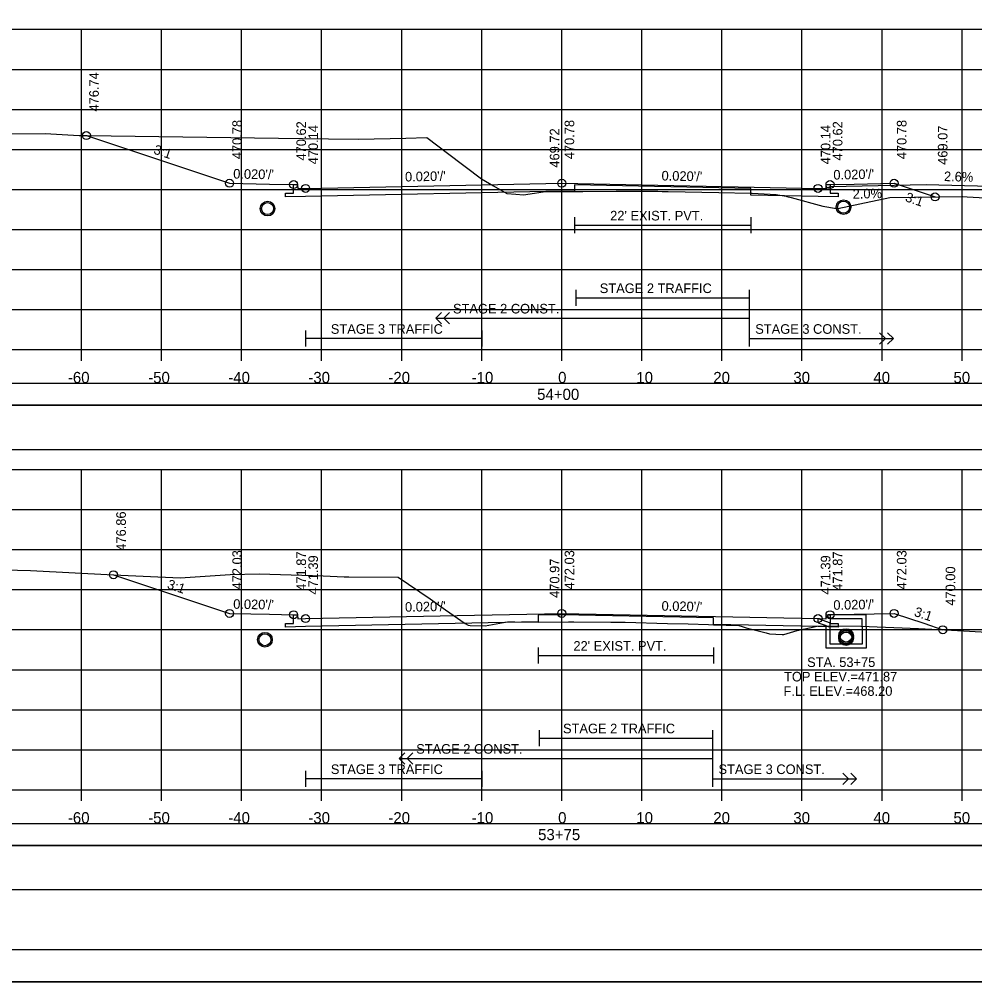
# Model space of a CAD drawing. Extents: x 1371057 to 1372761, y 380005 to 390517.
# Drawn here: x 1371826.4 to 1371945.8, y 383631.8 to 383752.1 of the extents above; entities that cross this region are included whole.
import ezdxf

# ---------------------------------------------------------------- set-up
doc = ezdxf.new("R2010")
doc.units = 0
for name, color, linetype in [('R_Alt Surface', 7, 'Continuous'), ('R_Axis', 7, 'Continuous'), ('R_Axis Annot', 7, 'Continuous'), ('R_Border', 7, 'Continuous'), ('R_Detour', 7, 'Continuous'), ('R_Dimension', 7, 'Continuous'), ('R_Drive', 7, 'Continuous'), ('R_Exist Surface', 7, 'Continuous'), ('R_Fin Surface', 7, 'Continuous'), ('R_Grid', 7, 'Continuous'), ('R_No Plot', 7, 'Continuous'), ('R_Striping', 7, 'Continuous'), ('R_Water', 7, 'Continuous'), ('R_Water Annot', 7, 'Continuous'), ('R_Xsect Elev', 7, 'Continuous'), ('R_Xsect Slope', 7, 'Continuous')]:
    doc.layers.add(name, color=color, linetype=linetype)

msp = doc.modelspace()

# ---------------------------------------------------------------- linework, layer by layer
at = {"layer": 'R_Alt Surface'}
for points in [[(1371927.71, 383731.42), (1371927.71, 383730.34), (1371928.71, 383730.32), (1371928.71, 383729.89), (1371926.21, 383729.94), (1371917.81, 383730.11), (1371917.81, 383730.94), (1371895.79, 383731.38), (1371895.79, 383730.55), (1371894.21, 383730.58), (1371862.21, 383729.94), (1371859.71, 383729.89), (1371859.71, 383730.32), (1371860.71, 383730.34), (1371860.71, 383731.42)], [(1371895.79, 383727.33), (1371895.79, 383725.33)], [(1371917.81, 383727.33), (1371917.81, 383725.33)], [(1371895.79, 383726.33), (1371917.81, 383726.33)], [(1371927.71, 383677.67), (1371927.71, 383676.59), (1371928.71, 383676.57), (1371928.71, 383676.14), (1371926.21, 383676.19), (1371913.17, 383676.45), (1371913.17, 383677.28), (1371894.21, 383677.66), (1371891.24, 383677.6), (1371891.24, 383676.77), (1371862.21, 383676.19), (1371859.71, 383676.14), (1371859.71, 383676.57), (1371860.71, 383676.59), (1371860.71, 383677.67)], [(1371891.24, 383673.58), (1371891.24, 383671.58)], [(1371913.17, 383673.58), (1371913.17, 383671.58)], [(1371891.24, 383672.58), (1371913.17, 383672.58)]]:
    msp.add_lwpolyline(points, dxfattribs=at)
at = {"layer": 'R_Axis'}
for p, q in [((1371744.21, 383710.81), (1372044.21, 383710.81)), ((1371834.21, 383709.41), (1371834.21, 383710.81)), ((1371844.21, 383709.41), (1371844.21, 383710.81)), ((1371854.21, 383709.41), (1371854.21, 383710.81)), ((1371864.21, 383709.41), (1371864.21, 383710.81)), ((1371874.21, 383709.41), (1371874.21, 383710.81)), ((1371884.21, 383709.41), (1371884.21, 383710.81)), ((1371894.21, 383709.41), (1371894.21, 383710.81)), ((1371904.21, 383709.41), (1371904.21, 383710.81)), ((1371914.21, 383709.41), (1371914.21, 383710.81)), ((1371924.21, 383709.41), (1371924.21, 383710.81)), ((1371934.21, 383709.41), (1371934.21, 383710.81)), ((1371944.21, 383709.41), (1371944.21, 383710.81)), ((1371744.21, 383655.81), (1372044.21, 383655.81)), ((1371834.21, 383654.41), (1371834.21, 383655.81)), ((1371844.21, 383654.41), (1371844.21, 383655.81)), ((1371854.21, 383654.41), (1371854.21, 383655.81)), ((1371864.21, 383654.41), (1371864.21, 383655.81)), ((1371874.21, 383654.41), (1371874.21, 383655.81)), ((1371884.21, 383654.41), (1371884.21, 383655.81)), ((1371894.21, 383654.41), (1371894.21, 383655.81)), ((1371904.21, 383654.41), (1371904.21, 383655.81)), ((1371914.21, 383654.41), (1371914.21, 383655.81)), ((1371924.21, 383654.41), (1371924.21, 383655.81)), ((1371934.21, 383654.41), (1371934.21, 383655.81)), ((1371944.21, 383654.41), (1371944.21, 383655.81))]:
    msp.add_line(p, q, dxfattribs=at)
at = {"layer": 'R_Border'}
msp.add_line((1372052.39, 383635.81), (1371736.21, 383635.81), dxfattribs=at)
at = {"layer": 'R_Detour'}
for points in [[(1371741.06, 383703.85), (1372047.37, 383703.85), (1372047.37, 383706.56), (1371741.06, 383706.56)], [(1371741.06, 383648.85), (1372047.37, 383648.85), (1372047.37, 383651.56), (1371741.06, 383651.56)]]:
    msp.add_lwpolyline(points, close=True, dxfattribs=at)
at = {"layer": 'R_Dimension'}
for points in [[(1371741.06, 383698.33), (1372047.37, 383698.33), (1372047.37, 383703.85), (1371741.06, 383703.85)], [(1371741.06, 383643.33), (1372047.37, 383643.33), (1372047.37, 383648.85), (1371741.06, 383648.85)]]:
    msp.add_lwpolyline(points, close=True, dxfattribs=at)
at = {"layer": 'R_Drive'}
for p, q in [((1371927.21, 383730.92), (1371927.71, 383731.17)), ((1371927.71, 383731.17), (1371939.71, 383731.41)), ((1371939.71, 383731.41), (1371947.7, 383731.2))]:
    msp.add_line(p, q, dxfattribs=at)
at = {"layer": 'R_Exist Surface'}
for points in [[(1371824.35, 383737.77), (1371829.69, 383737.8), (1371833.91, 383737.56), (1371834.08, 383737.54), (1371834.25, 383737.54), (1371834.29, 383737.54), (1371834.94, 383737.54), (1371861.84, 383737.19), (1371865.09, 383737.14), (1371868.81, 383737.09), (1371874.73, 383737.2), (1371877.35, 383737.31), (1371879.92, 383735.35), (1371884.16, 383732.13), (1371885.68, 383731.25), (1371887.33, 383730.28), (1371888.47, 383730.2), (1371889.43, 383730.12), (1371890.78, 383730.34), (1371891.87, 383730.52), (1371894.15, 383730.53), (1371895.79, 383730.53), (1371896.85, 383730.54), (1371901.01, 383730.57), (1371901.75, 383730.57), (1371906.09, 383730.57), (1371906.19, 383730.57), (1371906.74, 383730.55), (1371907.48, 383730.54), (1371913.84, 383730.41), (1371917.79, 383730.33), (1371917.81, 383730.33), (1371917.97, 383730.32), (1371920.97, 383730.16), (1371921.2, 383730.15), (1371922.25, 383729.95), (1371922.26, 383729.95), (1371922.31, 383729.94), (1371922.86, 383729.81), (1371926.83, 383728.73), (1371928.5, 383728.44), (1371928.7, 383728.42), (1371931.43, 383729.01), (1371935.17, 383729.81), (1371944.29, 383729.91), (1371944.86, 383729.89), (1371951.5, 383729.52)], [(1371811.46, 383683.61), (1371827.85, 383683.21), (1371838.23, 383682.66), (1371846.55, 383682.29), (1371852.8, 383682.69), (1371856.4, 383682.78), (1371864.39, 383682.54), (1371867.03, 383682.41), (1371867.62, 383682.39), (1371873.77, 383682.36), (1371877.76, 383679.66), (1371879.69, 383678.3), (1371882.13, 383676.57), (1371882.5, 383676.36), (1371882.78, 383676.34), (1371884.65, 383676.28), (1371886.92, 383676.7), (1371887.41, 383676.78), (1371888.35, 383676.78), (1371891.24, 383676.76), (1371895.06, 383676.78), (1371895.71, 383676.79), (1371900.34, 383676.76), (1371901.27, 383676.76), (1371901.48, 383676.75), (1371902.12, 383676.74), (1371907.43, 383676.59), (1371909.99, 383676.54), (1371912.52, 383676.45), (1371913.17, 383676.43), (1371914.72, 383676.39), (1371916.32, 383676.33), (1371916.75, 383676.19), (1371917.25, 383676.02), (1371919.73, 383675.41), (1371920.17, 383675.3), (1371921.75, 383675.22), (1371921.95, 383675.2), (1371923.6, 383675.69), (1371926.11, 383676.25), (1371926.93, 383676.27), (1371931.56, 383676.25), (1371938.76, 383675.97), (1371942.87, 383675.74), (1371948.1, 383675.45)]]:
    msp.add_lwpolyline(points, dxfattribs=at)
at = {"layer": 'R_Fin Surface'}
for points in [[(1371834.83, 383737.54), (1371834.84, 383737.54), (1371845.84, 383733.87), (1371852.7, 383731.58), (1371852.71, 383731.58), (1371852.71, 383731.58), (1371852.71, 383731.58), (1371857.71, 383731.48), (1371860.71, 383731.42), (1371861, 383731.42), (1371861.21, 383731.42), (1371861.22, 383730.92), (1371862.21, 383730.94), (1371862.23, 383730.94), (1371894.21, 383731.58), (1371894.22, 383731.58), (1371926.21, 383730.94), (1371927.21, 383730.92), (1371927.21, 383731.03), (1371927.21, 383731.42), (1371927.71, 383731.42), (1371930.71, 383731.48), (1371935.71, 383731.58), (1371940.83, 383729.88)], [(1371838.21, 383682.67), (1371844.7, 383680.5), (1371852.71, 383677.83), (1371852.71, 383677.83), (1371855.38, 383677.78), (1371857.71, 383677.73), (1371860.71, 383677.67), (1371861.21, 383677.67), (1371861.22, 383677.17), (1371862.21, 383677.19), (1371862.21, 383677.19), (1371881.14, 383677.57), (1371894.21, 383677.83), (1371894.21, 383677.83), (1371926.21, 383677.19), (1371926.21, 383677.19), (1371926.39, 383677.19), (1371927.21, 383677.17), (1371927.21, 383677.4), (1371927.21, 383677.67), (1371927.71, 383677.67), (1371928.99, 383677.7), (1371930.71, 383677.73), (1371935.71, 383677.83), (1371939.42, 383676.6), (1371941.8, 383675.8), (1371941.8, 383675.8)]]:
    msp.add_lwpolyline(points, dxfattribs=at)
at = {"layer": 'R_Grid'}
for p, q in [((1371744.21, 383750.81), (1372044.21, 383750.81)), ((1371834.21, 383710.81), (1371834.21, 383750.81)), ((1371844.21, 383710.81), (1371844.21, 383750.81)), ((1371854.21, 383710.81), (1371854.21, 383750.81)), ((1371864.21, 383710.81), (1371864.21, 383750.81)), ((1371874.21, 383710.81), (1371874.21, 383750.81)), ((1371884.21, 383710.81), (1371884.21, 383750.81)), ((1371894.21, 383710.81), (1371894.21, 383750.81)), ((1371904.21, 383710.81), (1371904.21, 383750.81)), ((1371914.21, 383710.81), (1371914.21, 383750.81)), ((1371924.21, 383710.81), (1371924.21, 383750.81)), ((1371934.21, 383710.81), (1371934.21, 383750.81)), ((1371944.21, 383710.81), (1371944.21, 383750.81)), ((1371744.21, 383745.81), (1372044.21, 383745.81)), ((1371744.21, 383740.81), (1372044.21, 383740.81)), ((1371744.21, 383735.81), (1372044.21, 383735.81)), ((1371744.21, 383730.81), (1372044.21, 383730.81)), ((1371744.21, 383725.81), (1372044.21, 383725.81)), ((1371744.21, 383720.81), (1372044.21, 383720.81)), ((1371744.21, 383715.81), (1372044.21, 383715.81)), ((1371744.21, 383710.81), (1372044.21, 383710.81)), ((1371744.21, 383695.81), (1372044.21, 383695.81)), ((1371834.21, 383655.81), (1371834.21, 383695.81)), ((1371844.21, 383655.81), (1371844.21, 383695.81)), ((1371854.21, 383655.81), (1371854.21, 383695.81)), ((1371864.21, 383655.81), (1371864.21, 383695.81)), ((1371874.21, 383655.81), (1371874.21, 383695.81)), ((1371884.21, 383655.81), (1371884.21, 383695.81)), ((1371894.21, 383655.81), (1371894.21, 383695.81)), ((1371904.21, 383655.81), (1371904.21, 383695.81)), ((1371914.21, 383655.81), (1371914.21, 383695.81)), ((1371924.21, 383655.81), (1371924.21, 383695.81)), ((1371934.21, 383655.81), (1371934.21, 383695.81)), ((1371944.21, 383655.81), (1371944.21, 383695.81)), ((1371744.21, 383690.81), (1372044.21, 383690.81)), ((1371744.21, 383685.81), (1372044.21, 383685.81)), ((1371744.21, 383680.81), (1372044.21, 383680.81)), ((1371744.21, 383675.81), (1372044.21, 383675.81)), ((1371744.21, 383670.81), (1372044.21, 383670.81)), ((1371744.21, 383665.81), (1372044.21, 383665.81)), ((1371744.21, 383660.81), (1372044.21, 383660.81)), ((1371744.21, 383655.81), (1372044.21, 383655.81))]:
    msp.add_line(p, q, dxfattribs=at)
at = {"layer": 'R_No Plot'}
msp.add_line((1371723.81, 383631.83), (1372057.14, 383631.83), dxfattribs=at)
for points in [[(1371723.8, 383845.16), (1372057.14, 383845.16), (1372057.14, 383631.82), (1371723.8, 383631.82)], [(1371970.13, 383841.27), (1371989.75, 383841.27), (1371989.75, 383831.39), (1372005.86, 383831.39), (1372029.06, 383831.39), (1372029.18, 383803.23), (1372052.39, 383803.23), (1372052.39, 383635.81), (1371736.21, 383635.81), (1371736.21, 383841.27)]]:
    msp.add_lwpolyline(points, close=True, dxfattribs=at)
for centre, radius in [((1371834.83, 383737.54), 0.5), ((1371852.71, 383731.58), 0.5), ((1371860.71, 383731.42), 0.5), ((1371894.21, 383731.58), 0.5), ((1371927.71, 383731.42), 0.5), ((1371935.71, 383731.58), 0.5), ((1371862.21, 383730.94), 0.5), ((1371926.21, 383730.94), 0.5), ((1371929.4, 383728.59), 0.917), ((1371940.83, 383729.88), 0.5), ((1371857.46, 383728.41), 0.917), ((1371838.21, 383682.67), 0.5), ((1371852.71, 383677.83), 0.5), ((1371860.71, 383677.67), 0.5), ((1371894.21, 383677.83), 0.5), ((1371927.71, 383677.67), 0.5), ((1371935.71, 383677.83), 0.5), ((1371862.21, 383677.19), 0.5), ((1371926.21, 383677.19), 0.5), ((1371857.13, 383674.55), 0.917), ((1371929.71, 383675.01), 0.917), ((1371929.71, 383674.76), 0.917), ((1371941.8, 383675.8), 0.5)]:
    msp.add_circle(centre, radius, dxfattribs=at)
at = {"layer": 'R_Striping'}
for p, q in [((1371895.98, 383718.26), (1371895.98, 383716.26)), ((1371917.62, 383718.26), (1371917.62, 383711.17)), ((1371895.98, 383717.26), (1371917.62, 383717.26)), ((1371878.49, 383714.71), (1371879.2, 383715.42)), ((1371879.49, 383714.71), (1371880.2, 383715.42)), ((1371878.49, 383714.71), (1371917.62, 383714.71)), ((1371879.2, 383714), (1371878.49, 383714.71)), ((1371880.2, 383714), (1371879.49, 383714.71)), ((1371862.21, 383713.17), (1371862.21, 383711.17)), ((1371884.21, 383713.17), (1371884.21, 383711.17)), ((1371934.62, 383712.17), (1371933.91, 383712.88)), ((1371935.62, 383712.17), (1371934.91, 383712.88)), ((1371884.21, 383712.17), (1371862.21, 383712.17)), ((1371917.62, 383712.17), (1371935.62, 383712.17)), ((1371917.65, 383712.17), (1371927.65, 383712.17)), ((1371933.91, 383711.46), (1371934.62, 383712.17)), ((1371934.91, 383711.46), (1371935.62, 383712.17)), ((1371891.39, 383663.26), (1371891.39, 383661.26)), ((1371891.39, 383662.26), (1371913.02, 383662.26)), ((1371913.02, 383663.26), (1371913.02, 383656.17)), ((1371873.9, 383659.71), (1371874.61, 383660.42)), ((1371874.9, 383659.71), (1371875.61, 383660.42)), ((1371873.9, 383659.71), (1371913.02, 383659.71)), ((1371874.61, 383659), (1371873.9, 383659.71)), ((1371875.61, 383659), (1371874.9, 383659.71)), ((1371862.21, 383658.17), (1371862.21, 383656.17)), ((1371884.21, 383658.17), (1371884.21, 383656.17)), ((1371930.02, 383657.17), (1371929.31, 383657.88)), ((1371931.02, 383657.17), (1371930.31, 383657.88)), ((1371884.21, 383657.17), (1371862.21, 383657.17)), ((1371913.02, 383657.17), (1371931.02, 383657.17)), ((1371913.05, 383657.17), (1371923.05, 383657.17)), ((1371929.31, 383656.46), (1371930.02, 383657.17)), ((1371930.31, 383656.46), (1371931.02, 383657.17))]:
    msp.add_line(p, q, dxfattribs=at)
at = {"layer": 'R_Water'}
for p, q in [((1371926.21, 383677.19), (1371927.71, 383676.67)), ((1371926.21, 383676.66), (1371927.21, 383676.32)), ((1371927.38, 383677.51), (1371927.46, 383677.67)), ((1371927.38, 383677.51), (1371927.71, 383677.17)), ((1371932.21, 383677.67), (1371927.46, 383677.67)), ((1371931.71, 383677.17), (1371927.71, 383677.17)), ((1371927.71, 383676.17), (1371927.71, 383676.67)), ((1371931.71, 383676.17), (1371931.71, 383677.17)), ((1371932.21, 383676.17), (1371932.21, 383677.67)), ((1371927.21, 383676.17), (1371927.21, 383676.32))]:
    msp.add_line(p, q, dxfattribs=at)
for points in [[(1371926.21, 383676.66), (1371926.21, 383677.19)], [(1371932.21, 383676.17), (1371932.21, 383673.51), (1371929.71, 383673.51), (1371927.21, 383673.51), (1371927.21, 383676.17)], [(1371931.71, 383676.17), (1371931.71, 383674.01), (1371929.71, 383674.01), (1371927.71, 383674.01), (1371927.71, 383676.17)]]:
    msp.add_lwpolyline(points, dxfattribs=at)
for centre in [(1371857.46, 383728.41), (1371929.4, 383728.59), (1371929.71, 383675.01), (1371929.71, 383674.76), (1371857.13, 383674.55)]:
    msp.add_circle(centre, 0.75, dxfattribs=at)
at = {"layer": 'R_Xsect Elev'}
for p, q in [((1371894.21, 383730.53), (1371894.21, 383740.53)), ((1371894.21, 383676.78), (1371894.21, 383686.78))]:
    msp.add_line(p, q, dxfattribs=at)

# ---------------------------------------------------------------- texts
at = {"layer": 'R_Axis Annot'}
for s, p in [('-60', (1371832.52, 383706.61)), ('-50', (1371842.55, 383706.61)), ('-40', (1371852.55, 383706.61)), ('-30', (1371862.55, 383706.61)), ('-20', (1371872.55, 383706.61)), ('-10', (1371882.95, 383706.61)), ('0', (1371893.75, 383706.61)), ('10', (1371903.52, 383706.61)), ('20', (1371913.13, 383706.61)), ('30', (1371923.13, 383706.61)), ('40', (1371933.13, 383706.61)), ('50', (1371943.13, 383706.61)), ('54+00', (1371891.13, 383704.51)), ('-60', (1371832.52, 383651.61)), ('-50', (1371842.55, 383651.61)), ('-40', (1371852.55, 383651.61)), ('-30', (1371862.55, 383651.61)), ('-20', (1371872.55, 383651.61)), ('-10', (1371882.95, 383651.61)), ('0', (1371893.75, 383651.61)), ('10', (1371903.52, 383651.61)), ('20', (1371913.13, 383651.61)), ('30', (1371923.13, 383651.61)), ('40', (1371933.13, 383651.61)), ('50', (1371943.13, 383651.61)), ('53+75', (1371891.25, 383649.51))]:
    msp.add_text(s, height=1.4, dxfattribs=at).set_placement(p)
at = {"layer": 'R_Striping'}
for s, p in [('STAGE 2 TRAFFIC', (1371898.95, 383717.86)), ('STAGE 2 CONST.', (1371880.62, 383715.31)), ('STAGE 3 TRAFFIC', (1371865.36, 383712.77)), ('STAGE 3 CONST.', (1371918.37, 383712.77)), ('STAGE 2 TRAFFIC', (1371894.36, 383662.86)), ('STAGE 2 CONST.', (1371876.02, 383660.31)), ('STAGE 3 TRAFFIC', (1371865.36, 383657.77)), ('STAGE 3 CONST.', (1371913.78, 383657.77))]:
    msp.add_text(s, height=1.2, dxfattribs=at).set_placement(p)
at = {"layer": 'R_Water'}
for p in [(1371900.25, 383726.93), (1371895.66, 383673.18)]:
    msp.add_text("22' EXIST. PVT.", height=1.2, dxfattribs=at).set_placement(p)
at = {"layer": 'R_Water Annot'}
for s, p in [('STA. 53+75', (1371924.85, 383671.14)), ('TOP ELEV.=471.87', (1371921.97, 383669.34)), ('F.L. ELEV.=468.20', (1371921.9, 383667.54))]:
    msp.add_text(s, height=1.2, dxfattribs=at).set_placement(p)
at = {"layer": 'R_Xsect Elev'}
for s, rotation, p in [('476.74', 90, (1371836.38, 383740.54)), ('470.78', 90, (1371854.26, 383734.58)), ('470.62', 90, (1371862.26, 383734.42)), ('470.78', 90, (1371895.76, 383734.58)), ('470.62', 90, (1371929.26, 383734.42)), ('470.78', 90, (1371937.26, 383734.58)), ('470.14', 90, (1371863.76, 383733.94)), ('469.72', 90, (1371893.91, 383733.53)), ('470.14', 90, (1371927.76, 383733.94)), ('469.07', 90, (1371942.38, 383733.88)), ('2.6%', 358.5106, (1371941.93, 383731.85)), ('2.0%', 1.1458, (1371930.55, 383729.65)), ('476.86', 90, (1371839.76, 383685.67)), ('472.03', 90, (1371854.26, 383680.83)), ('471.87', 90, (1371862.26, 383680.67)), ('471.39', 90, (1371863.76, 383680.19)), ('472.03', 90, (1371895.76, 383680.83)), ('471.39', 90, (1371927.76, 383680.19)), ('471.87', 90, (1371929.26, 383680.67)), ('472.03', 90, (1371937.26, 383680.83)), ('470.97', 90, (1371893.91, 383679.78)), ('470.00', 90, (1371943.35, 383678.8))]:
    msp.add_text(s, height=1.2, rotation=rotation, dxfattribs=at).set_placement(p)
at = {"layer": 'R_Xsect Slope'}
for s, rotation, p in [('3:1', 341.5663, (1371843.14, 383735.3)), ("0.020'/'", 358.8543, (1371853.16, 383732.17)), ("0.020'/'", 1.1457, (1371874.64, 383731.79)), ("0.020'/'", 358.8542, (1371906.66, 383731.93)), ("0.020'/'", 1.1459, (1371928.14, 383732.03)), ('3:1', 341.5645, (1371937.02, 383729.35)), ('3:1', 341.5667, (1371844.83, 383680.99)), ("0.020'/'", 358.854, (1371853.16, 383678.42)), ("0.020'/'", 1.1458, (1371874.64, 383678.04)), ("0.020'/'", 358.8542, (1371906.66, 383678.18)), ("0.020'/'", 1.1457, (1371928.14, 383678.28)), ('3:1', 341.5668, (1371938.13, 383677.55))]:
    msp.add_text(s, height=1.2, rotation=rotation, dxfattribs=at).set_placement(p)

doc.saveas('drawing.dxf')
